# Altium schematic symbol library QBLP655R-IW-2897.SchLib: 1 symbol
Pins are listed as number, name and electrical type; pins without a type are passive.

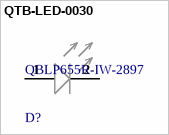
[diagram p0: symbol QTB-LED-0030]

## QTB-LED-0030
designator D?, comment QBLP655R-IW-2897
LED WHITE DIFFUSED 1205 SMD, REVERSE MOUNT; Manufacturer: QT Brightek (QTB); Lens Size: 1.2mm; Luminous Intensity: 370mcd; Test Current: 20mA; Lens Color: Yellow; Lens Style: Square with Flat Top; Forward Voltage: 3.1V; Viewing Angle: 140º
footprint QBLP655R-IW-2897
pins: 1 ANODE (+), 2 CATHODE (-)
